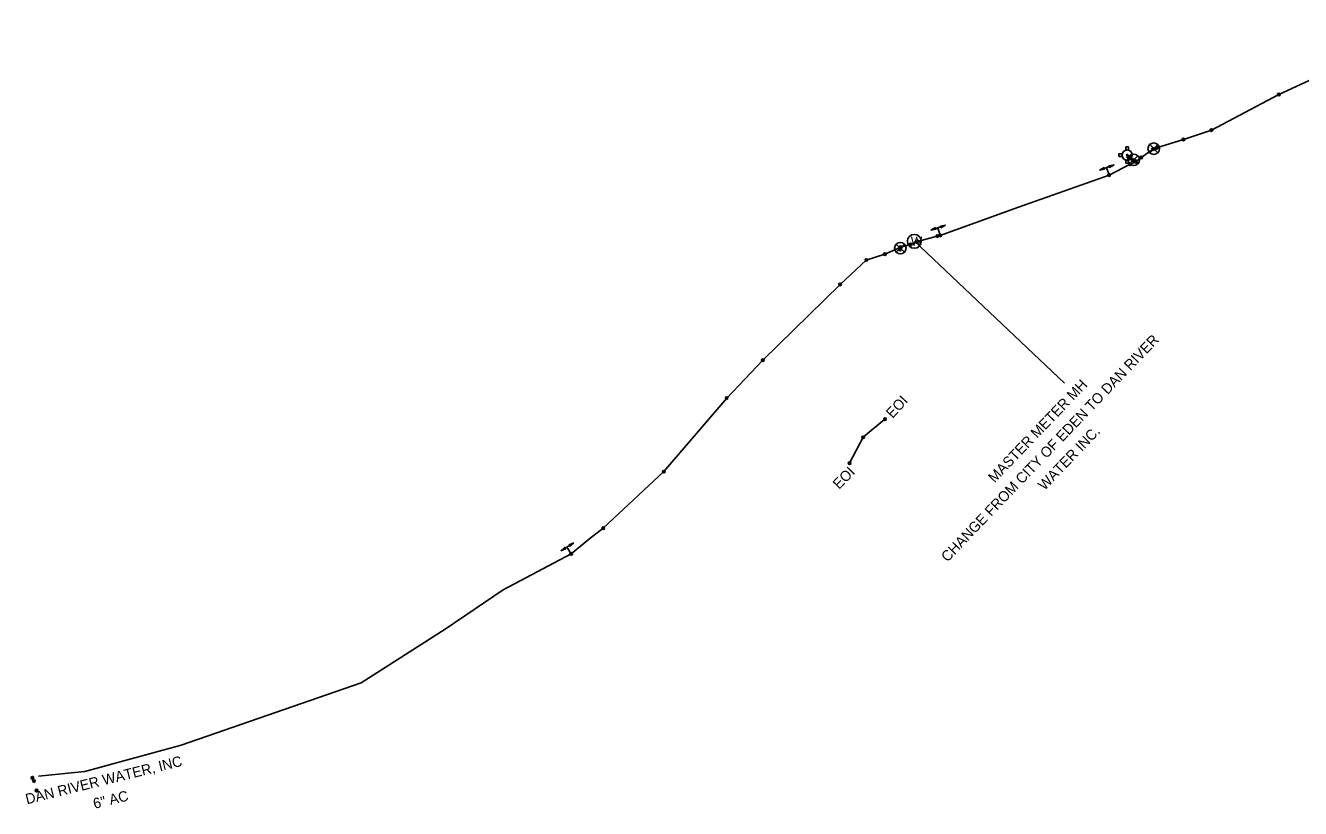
# Model space of a CAD drawing. Extents: x 1768541 to 1769517, y 999890 to 1000769.
# Drawn here: x 1768540.6 to 1769035.2, y 999889.9 to 1000193.7 of the extents above; entities that cross this region are included whole.
import ezdxf

# ---------------------------------------------------------------- set-up
doc = ezdxf.new("R2010")
doc.units = 0
for name, color, linetype in [('Default', 7, 'Continuous'), ('Exist Utilities Other Text', 7, 'Continuous'), ('Exist Utilities Other Unknown UG SUE LOS B', 7, 'Continuous'), ('Exist Utilities Water Change of Service SUE CELL', 7, 'Continuous'), ('Exist Utilities Water Fire Hydrant CELL', 7, 'Continuous'), ('Exist Utilities Water Manhole CELL', 7, 'Continuous'), ('Exist Utilities Water Test Hole SUE LOS A Leader', 7, 'Continuous'), ('Exist Utilities Water Text', 7, 'Continuous'), ('Exist Utilities Water UG Line SUE LOS B', 7, 'Continuous'), ('Exist Utilities Water UG Line SUE LOS C', 7, 'Continuous'), ('Exist Utilities Water Valve CELL', 7, 'Continuous')]:
    doc.layers.add(name, color=color, linetype=linetype)

# ---------------------------------------------------------------- blocks, each defined once
blk = doc.blocks.new('SurveyPointCell')
at = {"layer": 'Default'}
for p, q in [((-0.5, 0), (0.5, 0)), ((0, -0.5), (0, 0.5))]:
    blk.add_line(p, q, dxfattribs=at)
blk.add_circle((0, 0), 0.5, dxfattribs=at)

msp = doc.modelspace()

# ---------------------------------------------------------------- linework, layer by layer
at = {"layer": 'Exist Utilities Other Unknown UG SUE LOS B'}
msp.add_lwpolyline([(1768874.03, 1000040.94), (1768865.55, 1000033.91), (1768860.31, 1000023.9)], dxfattribs=at)
at = {"layer": 'Exist Utilities Water Change of Service SUE CELL'}
for p, q in [((1768962.9, 1000139.69), (1768957.31, 1000137.61)), ((1768959.96, 1000138.6), (1768962.9, 1000139.69)), ((1768961.04, 1000135.7), (1768959.96, 1000138.6)), ((1768961.04, 1000135.7), (1768961.04, 1000135.7)), ((1768897.52, 1000116.19), (1768891.85, 1000114.36)), ((1768894.54, 1000115.23), (1768897.52, 1000116.19)), ((1768895.49, 1000112.29), (1768894.54, 1000115.23)), ((1768895.49, 1000112.29), (1768895.49, 1000112.29)), ((1768753.33, 999992.97), (1768748.26, 999989.83)), ((1768750.66, 999991.31), (1768753.33, 999992.97)), ((1768752.29, 999988.69), (1768750.66, 999991.31)), ((1768752.29, 999988.69), (1768752.29, 999988.69))]:
    msp.add_line(p, q, dxfattribs=at)
for points in [[(1768957.31, 1000137.61), (1768959.04, 1000138.62), (1768958.76, 1000138.15), (1768959.23, 1000138)], [(1768962.9, 1000139.69), (1768961.17, 1000138.68), (1768961.44, 1000139.15), (1768960.98, 1000139.3)], [(1768891.85, 1000114.36), (1768893.62, 1000115.29), (1768893.33, 1000114.84), (1768893.78, 1000114.66)], [(1768897.52, 1000116.19), (1768895.76, 1000115.26), (1768896.05, 1000115.72), (1768895.59, 1000115.89)], [(1768748.26, 999989.83), (1768749.75, 999991.16), (1768749.58, 999990.64), (1768750.06, 999990.58)], [(1768753.33, 999992.97), (1768751.83, 999991.64), (1768752.01, 999992.15), (1768751.52, 999992.21)]]:
    msp.add_lwpolyline(points, close=True, dxfattribs=at)
for centre in [(1768961.04, 1000135.7), (1768895.49, 1000112.29), (1768752.29, 999988.69)]:
    msp.add_circle(centre, 0.517, dxfattribs=at)
at = {"layer": 'Exist Utilities Water Fire Hydrant CELL'}
msp.add_line((1768967.99, 1000143.44), (1768967.99, 1000143.44), dxfattribs=at)
for points in [[(1768966.08, 1000143.95), (1768964.79, 1000143.95), (1768964.79, 1000142.93), (1768966.08, 1000142.93)], [(1768967.48, 1000145.35), (1768967.48, 1000146.64), (1768968.5, 1000146.64), (1768968.5, 1000145.33)], [(1768967.48, 1000141.53), (1768967.48, 1000140.24), (1768968.5, 1000140.24), (1768968.5, 1000141.55)]]:
    msp.add_lwpolyline(points, dxfattribs=at)
for radius in [1.98, 0.243]:
    msp.add_circle((1768967.99, 1000143.44), radius, dxfattribs=at)
at = {"layer": 'Exist Utilities Water Manhole CELL'}
msp.add_line((1768885.43, 1000109.98), (1768885.43, 1000109.98), dxfattribs=at)
msp.add_circle((1768885.43, 1000109.98), 2.69, dxfattribs=at)
at = {"layer": 'Exist Utilities Water Test Hole SUE LOS A Leader'}
msp.add_line((1768885.43, 1000109.98), (1768943.71, 1000054.91), dxfattribs=at)
at = {"layer": 'Exist Utilities Water UG Line SUE LOS B'}
for points in [[(1768961.04, 1000135.7), (1768969.18, 1000139.87), (1768971.35, 1000140.81), (1768973.43, 1000142.53), (1768978.1, 1000145.76), (1768979.43, 1000146.23), (1768989.82, 1000149.51), (1769000.69, 1000153.15), (1769026.85, 1000166.94), (1769043.64, 1000174.71), (1769060.72, 1000180.57), (1769071.68, 1000183.46), (1769084.16, 1000186.77), (1769091.58, 1000191.19), (1769094.55, 1000193.73)], [(1768971.15, 1000141.07), (1768970.48, 1000141.43), (1768970.16, 1000141.47), (1768969.1, 1000142.6), (1768968.43, 1000142.73)], [(1768752.29, 999988.67), (1768759.47, 999994.66), (1768764.76, 999998.63), (1768788.26, 1000020.59), (1768812.62, 1000049.14), (1768826.64, 1000063.82), (1768856.62, 1000093.25), (1768866.8, 1000102.71), (1768873.99, 1000105.01), (1768880.15, 1000107.7), (1768883.97, 1000108.76), (1768886.66, 1000109.9), (1768894.33, 1000112.01), (1768895.49, 1000112.29)]]:
    msp.add_lwpolyline(points, dxfattribs=at)
at = {"layer": 'Exist Utilities Water UG Line SUE LOS C'}
for points in [[(1768895.49, 1000112.29), (1768925.82, 1000123.25), (1768961.04, 1000135.7)], [(1768545.59, 999902.47), (1768563.54, 999904.28), (1768600.96, 999914.47), (1768670.75, 999938.64), (1768703.43, 999959.42), (1768725.96, 999974.66), (1768752.29, 999988.69)]]:
    msp.add_lwpolyline(points, dxfattribs=at)
at = {"layer": 'Exist Utilities Water Valve CELL'}
for points in [[(1768979.88, 1000147.51), (1768976.73, 1000144.36), (1768978.3, 1000145.94), (1768979.88, 1000144.36), (1768976.73, 1000147.51)], [(1768972.11, 1000143.16), (1768968.96, 1000140.01), (1768970.54, 1000141.59), (1768972.11, 1000140.01), (1768968.96, 1000143.16)], [(1768881.57, 1000108.86), (1768878.43, 1000105.72), (1768880, 1000107.29), (1768881.57, 1000105.72), (1768878.43, 1000108.86)]]:
    msp.add_lwpolyline(points, dxfattribs=at)
for centre in [(1768970.54, 1000141.59), (1768978.3, 1000145.94), (1768880, 1000107.29)]:
    msp.add_circle(centre, 2.23, dxfattribs=at)

# ---------------------------------------------------------------- block references
at = {"layer": 'Default'}
for p in [(1769026.85, 1000166.94), (1769000.69, 1000153.15), (1768989.82, 1000149.51), (1768978.1, 1000145.76), (1768979.43, 1000146.23), (1768968.43, 1000142.73), (1768969.1, 1000142.6), (1768969.18, 1000139.87), (1768970.16, 1000141.47), (1768970.48, 1000141.43), (1768971.15, 1000141.07), (1768971.35, 1000140.81), (1768973.43, 1000142.53), (1768961.04, 1000135.7), (1768883.97, 1000108.76), (1768886.66, 1000109.9), (1768894.33, 1000112.01), (1768895.49, 1000112.29), (1768873.99, 1000105.01), (1768879.79, 1000106.78), (1768880.15, 1000107.7), (1768866.8, 1000102.71), (1768856.62, 1000093.25), (1768826.64, 1000063.82), (1768812.62, 1000049.14), (1768874.03, 1000040.94), (1768865.55, 1000033.91), (1768788.26, 1000020.59), (1768860.31, 1000023.9), (1768764.76, 999998.63), (1768752.29, 999988.67), (1768543.26, 999901.78), (1768543.86, 999900.51), (1768544.89, 999896.85)]:
    msp.add_blockref('SurveyPointCell', p, dxfattribs=at)

# ---------------------------------------------------------------- texts
at = {"layer": 'Exist Utilities Other Text'}
for rotation, p in [(47.3733, (1768876.98, 1000041.04)), (45.5005, (1768856.23, 1000013.49))]:
    msp.add_text('EOI', height=4.02, rotation=rotation, dxfattribs=at).set_placement(p)
at = {"layer": 'Exist Utilities Water Manhole CELL'}
msp.add_text('W', height=3.5, dxfattribs=at).set_placement((1768884.08, 1000108.23))
at = {"layer": 'Exist Utilities Water Text'}
for s, rotation, p in [('CHANGE FROM CITY OF EDEN TO DAN RIVER', 46.303, (1768898.3, 999985.28)), ('MASTER METER MH', 46.303, (1768916.55, 1000016.02)), ('WATER INC.', 46.303, (1768935.95, 1000013.05)), ('DAN RIVER WATER, INC', 13.9207, (1768541.12, 999891.46)), ('6" AC', 13.9207, (1768567.38, 999889.69))]:
    msp.add_text(s, height=4.02, rotation=rotation, dxfattribs=at).set_placement(p)

doc.saveas('drawing.dxf')
